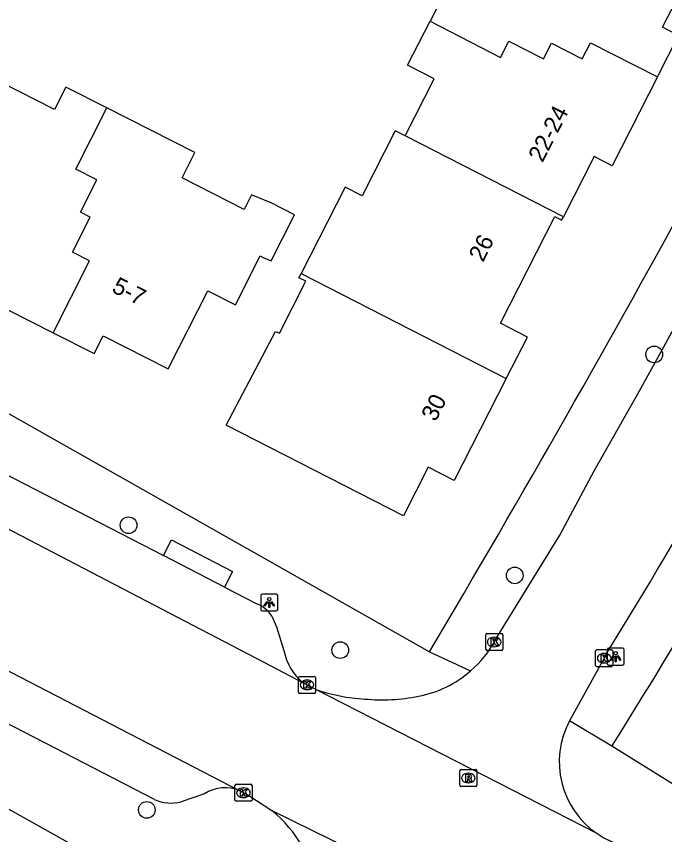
# Model space of a CAD drawing. Extents: x 160356 to 161355, y 381727 to 382845.
# Drawn here: x 160984.99 to 161023.07, y 382278.91 to 382326.97 of the extents above; entities that cross this region are included whole.
import ezdxf

# ---------------------------------------------------------------- set-up
doc = ezdxf.new("R2010")
doc.units = 0
for name, color, linetype in [('IMGEO_Boom', 7, 'Continuous'), ('IMGEO_Kolk', 7, 'Continuous'), ('IMGEO_Lichtpunt', 7, 'Continuous'), ('IMGEO_Pand', 7, 'Continuous'), ('IMGEO_Pand_nummerreeks', 7, 'Continuous'), ('IMGEO_Rijbaan_lokaal_open', 7, 'Continuous'), ('IMGEO_Rioolput', 7, 'Continuous'), ('IMGEO_Voetpad_open', 7, 'Continuous')]:
    doc.layers.add(name, color=color, linetype=linetype)

msp = doc.modelspace()

# ---------------------------------------------------------------- linework, layer by layer
at = {"layer": 'IMGEO_Boom'}
for centre in [(161022.458, 382307.11), (160991.58, 382297.081), (161014.264, 382294.133), (161004.018, 382289.744), (160992.651, 382280.362)]:
    msp.add_circle(centre, 0.489, dxfattribs=at)
at = {"layer": 'IMGEO_Kolk'}
for p, q in [((161012.557, 382289.794), (161012.557, 382290.646)), ((161012.632, 382290.72), (161013.484, 382290.72)), ((161013.045, 382290.5), (161013.07, 382290.5)), ((161013.558, 382290.646), (161013.558, 382289.794)), ((161013.484, 382289.72), (161012.632, 382289.72)), ((161013.068, 382289.94), (161013.043, 382289.94)), ((161019.018, 382288.847), (161019.018, 382289.699)), ((161019.093, 382289.773), (161019.945, 382289.773)), ((161019.506, 382289.553), (161019.531, 382289.553)), ((161020.019, 382289.699), (161020.019, 382288.847)), ((161019.945, 382288.773), (161019.093, 382288.773)), ((161019.529, 382288.993), (161019.504, 382288.993)), ((161001.561, 382287.278), (161001.561, 382288.13)), ((161001.636, 382288.204), (161002.488, 382288.204)), ((161002.562, 382288.13), (161002.562, 382287.278)), ((161002.049, 382287.984), (161002.074, 382287.984)), ((161002.488, 382287.204), (161001.636, 382287.204)), ((161002.072, 382287.424), (161002.047, 382287.424)), ((160997.904, 382281.868), (160998.756, 382281.868)), ((160997.829, 382280.942), (160997.829, 382281.794)), ((160998.317, 382281.648), (160998.342, 382281.648)), ((160998.83, 382281.794), (160998.83, 382280.942)), ((160998.34, 382281.088), (160998.315, 382281.088)), ((160998.756, 382280.868), (160997.904, 382280.868))]:
    msp.add_line(p, q, dxfattribs=at)
for points in [[(161012.557, 382289.794), (161012.557, 382290.646)], [(161012.632, 382290.72), (161013.484, 382290.72)], [(161013.558, 382290.646), (161013.558, 382289.794)], [(161012.878, 382290.42), (161013.001, 382290.42), (161013.001, 382290.269), (161013.131, 382290.42), (161013.295, 382290.42), (161013.149, 382290.269), (161013.302, 382290.02), (161013.15, 382290.02), (161013.065, 382290.184), (161013.001, 382290.117), (161013.001, 382290.02), (161012.878, 382290.02), (161012.878, 382290.42)], [(161013.484, 382289.72), (161012.632, 382289.72)], [(161019.018, 382288.847), (161019.018, 382289.699)], [(161019.093, 382289.773), (161019.945, 382289.773)], [(161020.019, 382289.699), (161020.019, 382288.847)], [(161019.339, 382289.473), (161019.462, 382289.473), (161019.462, 382289.322), (161019.592, 382289.473), (161019.756, 382289.473), (161019.61, 382289.322), (161019.763, 382289.073), (161019.611, 382289.073), (161019.526, 382289.237), (161019.462, 382289.17), (161019.462, 382289.073), (161019.339, 382289.073), (161019.339, 382289.473)], [(161019.945, 382288.773), (161019.093, 382288.773)], [(161001.561, 382287.278), (161001.561, 382288.13)], [(161001.636, 382288.204), (161002.488, 382288.204)], [(161002.562, 382288.13), (161002.562, 382287.278)], [(161001.882, 382287.904), (161002.005, 382287.904), (161002.005, 382287.753), (161002.135, 382287.904), (161002.299, 382287.904), (161002.153, 382287.753), (161002.306, 382287.504), (161002.154, 382287.504), (161002.069, 382287.668), (161002.005, 382287.601), (161002.005, 382287.504), (161001.882, 382287.504), (161001.882, 382287.904)], [(161002.488, 382287.204), (161001.636, 382287.204)], [(160997.904, 382281.868), (160998.756, 382281.868)], [(160997.829, 382280.942), (160997.829, 382281.794)], [(160998.15, 382281.568), (160998.273, 382281.568), (160998.273, 382281.417), (160998.403, 382281.568), (160998.567, 382281.568), (160998.421, 382281.417), (160998.574, 382281.168), (160998.422, 382281.168), (160998.337, 382281.332), (160998.273, 382281.265), (160998.273, 382281.168), (160998.15, 382281.168), (160998.15, 382281.568)], [(160998.83, 382281.794), (160998.83, 382280.942)], [(160998.756, 382280.868), (160997.904, 382280.868)]]:
    msp.add_lwpolyline(points, dxfattribs=at)
for centre, start, end in [((161012.634, 382290.644), 91.552, 178.448), ((161012.634, 382290.644), 91.552, 178.448), ((161013.482, 382290.644), 1.552, 88.448), ((161013.482, 382290.644), 1.552, 88.448), ((161012.634, 382289.796), 181.552, 268.448), ((161012.634, 382289.796), 181.552, 268.448), ((161013.482, 382289.796), 271.552, 358.448), ((161013.482, 382289.796), 271.552, 358.448), ((161019.095, 382289.697), 91.552, 178.448), ((161019.095, 382289.697), 91.552, 178.448), ((161019.943, 382289.697), 1.552, 88.448), ((161019.943, 382289.697), 1.552, 88.448), ((161019.095, 382288.849), 181.552, 268.448), ((161019.095, 382288.849), 181.552, 268.448), ((161019.943, 382288.849), 271.552, 358.448), ((161019.943, 382288.849), 271.552, 358.448), ((161001.638, 382288.128), 91.552, 178.448), ((161001.638, 382288.128), 91.552, 178.448), ((161002.486, 382288.128), 1.552, 88.448), ((161002.486, 382288.128), 1.552, 88.448), ((161001.638, 382287.28), 181.552, 268.448), ((161001.638, 382287.28), 181.552, 268.448), ((161002.486, 382287.28), 271.552, 358.448), ((161002.486, 382287.28), 271.552, 358.448), ((160997.906, 382281.792), 91.552, 178.448), ((160997.906, 382281.792), 91.552, 178.448), ((160998.754, 382281.792), 1.552, 88.448), ((160998.754, 382281.792), 1.552, 88.448), ((160997.906, 382280.944), 181.552, 268.448), ((160997.906, 382280.944), 181.552, 268.448), ((160998.754, 382280.944), 271.552, 358.448), ((160998.754, 382280.944), 271.552, 358.448)]:
    msp.add_arc(centre, 0.0765, start, end, dxfattribs=at)
for centre, major_axis, ratio, start_param, end_param in [((161013.044, 382290.22), (-0.387, 0.002), 0.722429, 4.712389, 7.853982), ((161013.069, 382290.22), (-0.39, 0.002), 0.717154, 1.570796, 4.712389), ((161019.505, 382289.273), (-0.387, 0.002), 0.722429, 4.712389, 7.853982), ((161019.53, 382289.273), (-0.39, 0.002), 0.717154, 1.570796, 4.712389), ((161002.048, 382287.704), (-0.387, 0.002), 0.722429, 4.712389, 7.853982), ((161002.073, 382287.704), (-0.39, 0.002), 0.717154, 1.570796, 4.712389), ((160998.316, 382281.368), (-0.387, 0.002), 0.722429, 4.712389, 7.853982), ((160998.341, 382281.368), (-0.39, 0.002), 0.717154, 1.570796, 4.712389)]:
    msp.add_ellipse(centre, major_axis=major_axis, ratio=ratio, start_param=start_param, end_param=end_param, dxfattribs=at)
at = {"layer": 'IMGEO_Lichtpunt'}
for p, q in [((160999.346, 382292.946), (160999.346, 382292.139)), ((160999.346, 382292.946), (160999.346, 382292.139)), ((161000.248, 382293.041), (160999.44, 382293.041)), ((161000.248, 382293.041), (160999.44, 382293.041)), ((161000.342, 382292.139), (161000.342, 382292.946)), ((161000.342, 382292.139), (161000.342, 382292.946)), ((160999.44, 382292.045), (161000.248, 382292.045)), ((160999.44, 382292.045), (161000.248, 382292.045)), ((161019.695, 382289.766), (161019.695, 382288.959)), ((161019.695, 382289.766), (161019.695, 382288.959)), ((161020.597, 382289.861), (161019.789, 382289.861)), ((161020.597, 382289.861), (161019.789, 382289.861)), ((161020.691, 382288.959), (161020.691, 382289.766)), ((161020.691, 382288.959), (161020.691, 382289.766)), ((161019.789, 382288.865), (161020.597, 382288.865)), ((161019.789, 382288.865), (161020.597, 382288.865))]:
    msp.add_line(p, q, dxfattribs=at)
for points in [[(160999.72, 382292.61), (160999.759, 382292.582), (160999.571, 382292.32), (160999.533, 382292.347), (160999.72, 382292.61)], [(160999.822, 382292.562), (160999.869, 382292.562), (160999.869, 382292.24), (160999.822, 382292.24), (160999.822, 382292.562)], [(160999.932, 382292.582), (160999.97, 382292.609), (161000.157, 382292.347), (161000.118, 382292.319), (160999.932, 382292.582)], [(161020.069, 382289.43), (161020.108, 382289.402), (161019.92, 382289.14), (161019.882, 382289.167), (161020.069, 382289.43)], [(161020.171, 382289.382), (161020.218, 382289.382), (161020.218, 382289.06), (161020.171, 382289.06), (161020.171, 382289.382)], [(161020.281, 382289.402), (161020.319, 382289.429), (161020.506, 382289.167), (161020.467, 382289.139), (161020.281, 382289.402)]]:
    msp.add_lwpolyline(points, dxfattribs=at)
for centre in [(160999.845, 382292.744), (161020.194, 382289.564)]:
    msp.add_circle(centre, 0.0994, dxfattribs=at)
for centre, start, end in [((160999.44, 382292.946), 90, 180), ((160999.44, 382292.946), 90, 180), ((161000.248, 382292.946), 0, 90), ((161000.248, 382292.946), 0, 90), ((160999.44, 382292.139), 180, 270), ((160999.44, 382292.139), 180, 270), ((161000.248, 382292.139), 270, 0), ((161000.248, 382292.139), 270, 360), ((161019.789, 382289.766), 90, 180), ((161019.789, 382289.766), 90, 180), ((161020.597, 382289.766), 0, 90), ((161020.597, 382289.766), 0, 90), ((161019.789, 382288.959), 180, 270), ((161019.789, 382288.959), 180, 270), ((161020.597, 382288.959), 270, 0), ((161020.597, 382288.959), 270, 360)]:
    msp.add_arc(centre, 0.0946, start, end, dxfattribs=at)
at = {"layer": 'IMGEO_Pand'}
for points in [[(161015.226, 382334.802), (161013.228, 382330.897), (161011.818, 382331.618), (161009.289, 382326.675)], [(161022.647, 382323.413), (161023.892, 382325.846), (161022.944, 382326.331), (161024.781, 382329.922)], [(161007.82, 382319.951), (161009.534, 382323.302), (161007.972, 382324.101), (161009.289, 382326.675)], [(161009.289, 382326.675), (161013.434, 382324.558), (161013.925, 382325.519), (161015.961, 382324.479), (161016.43, 382325.398), (161018.232, 382324.478), (161018.714, 382325.421), (161022.647, 382323.413)], [(160990.299, 382321.587), (160987.89, 382322.804), (160987.229, 382321.496), (160984.065, 382323.095), (160983.701, 382323.279), (160983.497, 382323.382), (160984.012, 382324.402), (160982.167, 382325.333), (160981.596, 382324.202), (160979.34, 382319.739), (160980.999, 382318.901), (160978.56, 382314.076), (160982.304, 382312.184), (160981.757, 382311.103), (160987.149, 382308.378)], [(161022.647, 382323.413), (161019.979, 382318.196), (161018.93, 382318.732), (161017.12, 382315.193)], [(160987.149, 382308.378), (160989.29, 382312.615), (160988.28, 382313.125), (160989.314, 382315.171), (160988.746, 382315.458), (160989.711, 382317.367), (160988.48, 382317.989), (160990.299, 382321.587)], [(160987.149, 382308.378), (160989.561, 382307.159), (160990.089, 382308.204), (160993.914, 382306.271), (160996.231, 382310.855), (160997.86, 382310.032), (160999.311, 382312.902), (160999.489, 382312.812), (160999.946, 382312.602), (161001.319, 382315.319), (161000, 382315.993), (160998.806, 382316.476), (160998.379, 382315.633), (160994.727, 382317.479), (160995.48, 382318.968), (160990.299, 382321.587)], [(161007.82, 382319.951), (161007.246, 382320.244), (161005.298, 382316.435), (161004.309, 382316.94), (161001.71, 382311.859)], [(161017.12, 382315.193), (161007.82, 382319.951)], [(161013.764, 382305.693), (161015.011, 382308.131), (161013.419, 382308.946), (161016.619, 382315.203), (161017.02, 382314.998), (161017.12, 382315.193)], [(161013.764, 382305.693), (161010.7, 382299.704), (161009.179, 382300.481), (161007.722, 382297.633), (160997.304, 382302.962), (160999.639, 382307.385), (161000.206, 382308.459), (161000.436, 382308.367), (161001.99, 382311.405), (161001.584, 382311.613), (161001.71, 382311.859)], [(161001.71, 382311.859), (161013.764, 382305.693)]]:
    msp.add_lwpolyline(points, dxfattribs=at)
at = {"layer": 'IMGEO_Rijbaan_lokaal_open'}
for points in [[(161013.122, 382290.331), (161016.914, 382296.501), (161018.936, 382300.269), (161021.499, 382304.793), (161023.03, 382307.549), (161025.1, 382311.349), (161027.416, 382315.541), (161030.38, 382320.921), (161032.376, 382324.549)], [(161001.819, 382287.83), (161000, 382288.778), (160981.577, 382298.373)], [(160978.184, 382291.798), (160998.118, 382281.479)], [(161019.634, 382289.507), (161019.52, 382289.272), (161017.487, 382285.598)], [(161002.583, 382287.432), (161001.819, 382287.83)], [(161019.106, 382278.967), (161002.583, 382287.432)], [(160998.118, 382281.479), (160998.634, 382281.212), (161000, 382280.323)], [(161000, 382280.323), (161016.444, 382272.241)]]:
    msp.add_lwpolyline(points, dxfattribs=at)
for centre, radius, start, end in [((160376.886, 382670.769), 672.189, 328.934463, 335.405026), ((160663.924, 382508.931), 417.943, 328.33115, 335.58077), ((161007.4, 382293.43), 6.507, 311.0664, 331.5598), ((161007.398, 382293.431), 6.509, 280.7469, 311.0739), ((161006.031, 382297.463), 10.607, 251.0312, 266.8493), ((161006.469, 382297.778), 10.953, 264.6517, 281.2827), ((161021.985, 382283.183), 5.105, 151.7677, 235.6737), ((160995.17, 382274.421), 7.626, 8.6173, 50.7012), ((161021.941, 382283.098), 5.01, 235.5379, 248.1703)]:
    msp.add_arc(centre, radius, start, end, dxfattribs=at)
at = {"layer": 'IMGEO_Rioolput'}
for p, q in [((161011.039, 382281.806), (161011.039, 382282.658)), ((161011.114, 382282.732), (161011.966, 382282.732)), ((161011.527, 382282.512), (161011.552, 382282.512)), ((161012.04, 382282.658), (161012.04, 382281.806)), ((161011.55, 382281.952), (161011.525, 382281.952)), ((161011.966, 382281.732), (161011.114, 382281.732))]:
    msp.add_line(p, q, dxfattribs=at)
for points in [[(161011.039, 382281.806), (161011.039, 382282.658)], [(161011.114, 382282.732), (161011.966, 382282.732)], [(161011.628, 382282.43), (161011.376, 382282.432), (161011.376, 382282.032)], [(161011.554, 382282.351), (161011.5, 382282.351), (161011.5, 382282.27)], [(161012.04, 382282.658), (161012.04, 382281.806)], [(161011.376, 382282.032), (161011.5, 382282.032), (161011.5, 382282.194), (161011.511, 382282.194)], [(161011.5, 382282.27), (161011.552, 382282.27)], [(161011.558, 382282.165), (161011.629, 382282.032), (161011.769, 382282.032), (161011.704, 382282.158)], [(161011.966, 382281.732), (161011.114, 382281.732)]]:
    msp.add_lwpolyline(points, dxfattribs=at)
for centre, radius, start, end in [((161011.116, 382282.656), 0.0765, 91.552, 178.448), ((161011.116, 382282.656), 0.0765, 91.552, 178.448), ((161011.56, 382282.255), 0.0964, 77.0061, 93.1865), ((161011.574, 382282.312), 0.0378, 276.6634, 79.6772), ((161011.627, 382282.32), 0.109, 350.3612, 89.416), ((161011.964, 382282.656), 0.0765, 1.552, 88.448), ((161011.964, 382282.656), 0.0765, 1.552, 88.448), ((161011.51, 382282.141), 0.0533, 26.0293, 88.6989), ((161011.536, 382282.459), 0.19, 274.7715, 282.9687), ((161011.625, 382282.32), 0.112, 277.5842, 350.9817), ((161011.609, 382282.105), 0.108, 29.5134, 73.7905), ((161011.116, 382281.808), 0.0765, 181.552, 268.448), ((161011.116, 382281.808), 0.0765, 181.552, 268.448), ((161011.964, 382281.808), 0.0765, 271.552, 358.448), ((161011.964, 382281.808), 0.0765, 271.552, 358.448)]:
    msp.add_arc(centre, radius, start, end, dxfattribs=at)
for centre, major_axis, ratio, start_param, end_param in [((161011.526, 382282.232), (-0.387, 0.002), 0.722429, 4.712389, 7.853982), ((161011.551, 382282.232), (-0.39, 0.002), 0.717154, 1.570796, 4.712389)]:
    msp.add_ellipse(centre, major_axis=major_axis, ratio=ratio, start_param=start_param, end_param=end_param, dxfattribs=at)
at = {"layer": 'IMGEO_Voetpad_open'}
for points in [[(160956.591, 382319.437), (161000, 382294.885), (161009.255, 382289.651)], [(160973.521, 382305.662), (160982.429, 382301.069), (160981.499, 382299.266), (160982.646, 382298.675), (160983.576, 382300.479), (160993.621, 382295.299)], [(160999.031, 382272.284), (160967.843, 382289.749), (160946.666, 382301.996)], [(160993.102, 382280.969), (160976.072, 382289.757), (160977.003, 382291.562), (160975.866, 382292.149), (160974.935, 382290.345), (160954.677, 382300.798)], [(160993.621, 382295.299), (160994.098, 382296.223), (160997.692, 382294.37), (160997.215, 382293.446)], [(160997.215, 382293.446), (160993.621, 382295.299)], [(160997.215, 382293.446), (160999.108, 382292.47)], [(161000, 382291.742), (161000.261, 382291.108), (161000.704, 382289.714)], [(161009.255, 382289.651), (161011.675, 382288.524)], [(161019.978, 382284.113), (161017.487, 382285.598)], [(161023.842, 382281.693), (161019.978, 382284.113)], [(160996.045, 382281.31), (160994.677, 382280.829)]]:
    msp.add_lwpolyline(points, dxfattribs=at)
for centre, radius, start, end in [((160652.334, 382514.455), 433.843, 327.93132, 333.95557), ((160248.207, 382741.334), 884.992, 329.310837, 331.381195), ((160998.422, 382290.719), 1.881, 32.9569, 68.6043), ((161003.892, 382290.329), 3.246, 190.9128, 230.3235), ((160997.236, 382279.496), 2.17, 66.0301, 123.2912), ((160994.099, 382283.257), 2.496, 246.4547, 283.3861)]:
    msp.add_arc(centre, radius, start, end, dxfattribs=at)

# ---------------------------------------------------------------- texts
at = {"layer": 'IMGEO_Pand_nummerreeks'}
for s, rotation, p in [('22-24', 62.9108, (161015.897, 382318.336)), ('26', 62.9108, (161012.401, 382312.488)), ('5-7', 333.1225, (160990.533, 382310.811)), ('30', 62.9055, (161009.615, 382303.116))]:
    msp.add_text(s, height=1, rotation=rotation, dxfattribs=at).set_placement(p)

doc.saveas('drawing.dxf')
